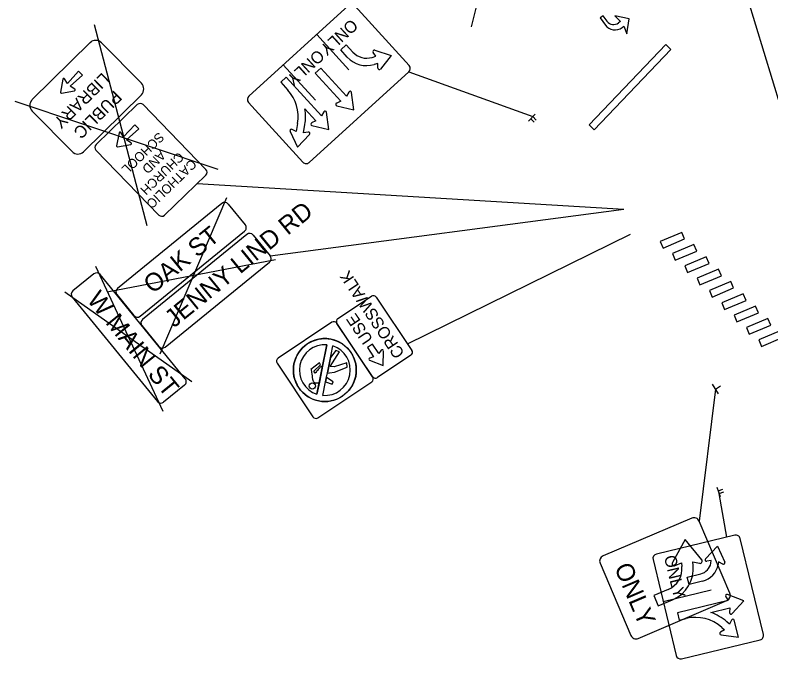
# Model space of a CAD drawing. Extents: x 1479394 to 1483660, y 379804 to 384342.
# Drawn here: x 1479394 to 1479604.6, y 379815.7 to 379995.2 of the extents above; entities that cross this region are included whole.
import ezdxf

# ---------------------------------------------------------------- set-up
doc = ezdxf.new("R2010")
doc.units = 0
for name, color, linetype in [('PM_P_Cells', 7, 'Continuous'), ('PM_P_Stop_Line', 7, 'Continuous'), ('RD_P_Text', 7, 'Continuous'), ('SC_Scratch15', 7, 'Continuous'), ('SC_Scratch3', 7, 'Continuous'), ('SH_Text', 7, 'Continuous')]:
    doc.layers.add(name, color=color, linetype=linetype)

msp = doc.modelspace()

# ---------------------------------------------------------------- linework, layer by layer
at = {"layer": 'PM_P_Cells'}
for p, q in [((1479557.84, 379995.03), (1479557.03, 379994.44)), ((1479557.03, 379994.44), (1479558.49, 379992.44)), ((1479558.94, 379993.53), (1479557.84, 379995.03)), ((1479565.07, 379994.18), (1479561.12, 379995.06)), ((1479561.12, 379995.06), (1479562.71, 379993.45)), ((1479564.44, 379989.95), (1479565.07, 379994.18)), ((1479562.71, 379993.45), (1479562.15, 379993.03)), ((1479563.12, 379991.76), (1479563.66, 379992.15)), ((1479563.66, 379992.15), (1479564.44, 379989.95)), ((1479564.44, 379989.95), (1479564.44, 379989.95))]:
    msp.add_line(p, q, dxfattribs=at)
for centre, radius, end in [((1479560.79, 379994.89), 2.3, 306.1769), ((1479561.14, 379994.38), 3.28, 307.0854)]:
    msp.add_arc(centre, radius, 216.1769, end, dxfattribs=at)
at = {"layer": 'PM_P_Stop_Line'}
msp.add_lwpolyline([(1479576.76, 379985.6), (1479575.34, 379987), (1479553.96, 379964.59), (1479555.4, 379963.2)], close=True, dxfattribs=at)
at = {"layer": 'RD_P_Text'}
for p, q in [((1479430.83, 379936.43), (1479416.15, 379992.52)), ((1479450.63, 379952.18), (1479394.05, 379971.11)), ((1479452.92, 379944.24), (1479434.33, 379900.66)), ((1479419.69, 379918.05), (1479466.63, 379927.1)), ((1479416.45, 379925.26), (1479435.18, 379884.77)), ((1479443.29, 379893.01), (1479407.91, 379917.97)), ((1479590.03, 379889.61), (1479588.31, 379892.31)), ((1479589.17, 379890.96), (1479590.52, 379891.82))]:
    msp.add_line(p, q, dxfattribs=at)
at = {"layer": 'SC_Scratch15'}
for p, q in [((1479578.23, 380065.44), (1479613.9, 379947.6)), ((1479487.06, 379979.98), (1479478.08, 379989.84)), ((1479484.77, 379985.51), (1479486.31, 379986.91)), ((1479486.59, 379983.51), (1479484.77, 379985.51)), ((1479486.31, 379986.91), (1479488.13, 379984.91)), ((1479494.25, 379985.44), (1479498.85, 379983.97)), ((1479493.49, 379983.43), (1479494.5, 379983.74)), ((1479494.5, 379983.74), (1479493.78, 379984.8)), ((1479498.85, 379983.97), (1479495.84, 379980.19)), ((1479477.74, 379971.5), (1479468.76, 379981.35)), ((1479495.11, 379981.74), (1479494.1, 379981.44)), ((1479495.09, 379980.46), (1479495.11, 379981.74)), ((1479479.22, 379980.46), (1479477.68, 379979.06)), ((1479477.68, 379979.06), (1479484.8, 379971.25)), ((1479486.34, 379972.65), (1479479.22, 379980.46)), ((1479503.73, 379979.39), (1479538.25, 379966.91)), ((1479469.59, 379977.88), (1479468.05, 379976.48)), ((1479479.37, 379967.15), (1479469.59, 379977.88)), ((1479468.05, 379976.48), (1479470.02, 379974.33)), ((1479486.99, 379973.77), (1479486.34, 379972.65)), ((1479488.42, 379968.82), (1479487.76, 379973.61)), ((1479484.8, 379971.25), (1479483.63, 379970.71)), ((1479474.79, 379969.08), (1479477.83, 379965.75)), ((1479480.02, 379968.26), (1479479.37, 379967.15)), ((1479483.71, 379969.92), (1479488.42, 379968.82)), ((1479481.45, 379963.32), (1479480.79, 379968.11)), ((1479537.03, 379965.63), (1479538.91, 379967.6)), ((1479537.69, 379966.32), (1479538.67, 379965.38)), ((1479537.97, 379966.61), (1479537.97, 379966.61)), ((1479537.97, 379966.61), (1479537.97, 379966.61)), ((1479538.25, 379966.91), (1479539.24, 379965.97)), ((1479472.74, 379965.03), (1479472.35, 379962.77)), ((1479474.41, 379962.42), (1479474.79, 379964.68)), ((1479477.83, 379965.75), (1479476.66, 379965.21)), ((1479476.74, 379964.42), (1479481.45, 379963.32)), ((1479470.64, 379962.81), (1479472.67, 379958.42)), ((1479472.35, 379962.77), (1479471.2, 379963.36)), ((1479475.68, 379962.59), (1479474.41, 379962.42)), ((1479472.67, 379958.42), (1479476.04, 379961.89)), ((1479503.38, 379903.52), (1479565.44, 379934.1)), ((1479478.13, 379889.51), (1479480.88, 379903.32)), ((1479493.65, 379903.47), (1479492.18, 379902.5)), ((1479481.78, 379897.22), (1479484.44, 379901.37)), ((1479481.78, 379897.22), (1479484.44, 379901.37)), ((1479483.39, 379901.73), (1479481.88, 379899.77)), ((1479483.39, 379901.73), (1479481.88, 379899.77)), ((1479484.44, 379901.37), (1479483.39, 379901.73)), ((1479484.44, 379901.37), (1479483.39, 379901.73)), ((1479492.18, 379902.5), (1479493.9, 379899.94)), ((1479496.06, 379901.78), (1479495.36, 379900.9)), ((1479496.58, 379897.5), (1479496.67, 379901.56)), ((1479481.88, 379899.77), (1479481.03, 379895.48)), ((1479492.8, 379898.97), (1479496.58, 379897.5)), ((1479493.9, 379899.93), (1479492.83, 379899.61)), ((1479493.9, 379899.94), (1479493.9, 379899.93)), ((1479494.69, 379900.33), (1479494.69, 379900.33)), ((1479478.83, 379898.25), (1479476.47, 379896.4)), ((1479478.83, 379898.25), (1479476.47, 379896.4)), ((1479477.23, 379895.97), (1479479.14, 379897.69)), ((1479477.23, 379895.97), (1479479.14, 379897.69)), ((1479478.8, 379892.91), (1479479.69, 379897.37)), ((1479479.14, 379897.69), (1479478.83, 379898.25)), ((1479479.14, 379897.69), (1479478.83, 379898.25)), ((1479482.93, 379897.13), (1479481.78, 379897.22)), ((1479482.93, 379897.13), (1479481.78, 379897.22)), ((1479486.45, 379898.22), (1479482.93, 379897.13)), ((1479486.45, 379898.22), (1479482.93, 379897.13)), ((1479482.99, 379895.68), (1479486.59, 379897.09)), ((1479482.99, 379895.68), (1479486.59, 379897.09)), ((1479486.59, 379897.09), (1479486.45, 379898.22)), ((1479486.59, 379897.09), (1479486.45, 379898.22)), ((1479476.47, 379896.4), (1479476.48, 379896.38)), ((1479476.47, 379896.4), (1479476.48, 379896.38)), ((1479477.62, 379895.35), (1479477.23, 379895.97)), ((1479477.62, 379895.35), (1479477.23, 379895.97)), ((1479481.03, 379895.48), (1479481.01, 379895.4)), ((1479481.01, 379895.4), (1479481.59, 379895.46)), ((1479481.01, 379895.4), (1479481.59, 379895.46)), ((1479481.59, 379895.46), (1479482.99, 379895.68)), ((1479481.59, 379895.46), (1479482.99, 379895.68)), ((1479478.77, 379892.76), (1479478.8, 379892.91)), ((1479480.53, 379892.98), (1479482.35, 379892.34)), ((1479480.53, 379892.98), (1479482.35, 379892.34)), ((1479480.76, 379894.13), (1479480.72, 379893.9)), ((1479482.61, 379893), (1479480.76, 379894.13)), ((1479482.61, 379893), (1479480.76, 379894.13)), ((1479482.35, 379892.34), (1479482.61, 379893)), ((1479482.35, 379892.34), (1479482.61, 379893)), ((1479589.17, 379890.96), (1479584.6, 379854.14)), ((1479590.51, 379860.91), (1479589.59, 379863.47)), ((1479589.91, 379862.57), (1479591.19, 379863.03)), ((1479590.05, 379862.19), (1479590.05, 379862.19)), ((1479590.05, 379862.19), (1479590.05, 379862.19)), ((1479590.19, 379861.8), (1479591.47, 379862.26)), ((1479592.33, 379849.65), (1479590.19, 379861.8)), ((1479580.69, 379848.97), (1479577.15, 379842.62)), ((1479585.33, 379843.37), (1479580.69, 379848.97)), ((1479586.35, 379843.64), (1479589.73, 379847.1)), ((1479589.73, 379847.1), (1479591.75, 379842.7)), ((1479577.93, 379841.73), (1479579.72, 379842.48)), ((1479579.72, 379842.48), (1479579.81, 379841.49)), ((1479582.92, 379841.78), (1479582.83, 379842.76)), ((1479582.83, 379842.76), (1479584.72, 379842.36)), ((1479587.98, 379843.11), (1479586.7, 379842.94)), ((1479587.86, 379842.43), (1479587.98, 379843.11)), ((1479590.03, 379842.75), (1479589.91, 379842.07)), ((1479591.18, 379842.16), (1479590.03, 379842.75)), ((1479581.3, 379838.52), (1479585.05, 379839.43)), ((1479581.79, 379836.5), (1479581.3, 379838.52)), ((1479585.54, 379837.4), (1479581.79, 379836.5)), ((1479575.97, 379835.07), (1479571.95, 379833.35)), ((1479587.97, 379834.88), (1479574.6, 379831.65)), ((1479597.04, 379831.93), (1479592.52, 379833.66)), ((1479571.95, 379833.35), (1479573.17, 379830.48)), ((1479573.17, 379830.48), (1479577.2, 379832.19)), ((1479592.68, 379831.95), (1479578.57, 379828.54)), ((1479592.02, 379833.05), (1479592.68, 379831.95)), ((1479593.81, 379828.33), (1479597.04, 379831.93)), ((1479587.88, 379828.65), (1479593.17, 379829.92)), ((1479593.17, 379829.92), (1479593.08, 379828.64)), ((1479578.57, 379828.54), (1479579.06, 379826.52)), ((1479579.06, 379826.52), (1479580.98, 379826.98)), ((1479593.06, 379825.37), (1479592.31, 379826.04)), ((1479593.59, 379826.55), (1479593.06, 379825.37)), ((1479595.53, 379821.78), (1479594.38, 379826.48)), ((1479591.67, 379823.82), (1479590.57, 379823.16)), ((1479590.92, 379824.49), (1479591.67, 379823.82)), ((1479590.73, 379822.39), (1479595.53, 379821.78))]:
    msp.add_line(p, q, dxfattribs=at)
for points in [[(1479486.89, 379997.87), (1479459.17, 379972.62)], [(1479503.81, 379981.16), (1479488.66, 379997.79)], [(1479476.01, 379954.14), (1479503.73, 379979.39)], [(1479459.09, 379970.85), (1479474.24, 379954.22)], [(1479483.97, 379910.59), (1479493.3, 379916.82)], [(1479494.67, 379916.55), (1479504.56, 379901.74)], [(1479482.26, 379909.57), (1479467.3, 379899.57)], [(1479493.65, 379894.33), (1479483.65, 379909.3)], [(1479493.6, 379894.41), (1479483.7, 379909.22)], [(1479480.87, 379903.32), (1479479.78, 379897.84), (1479479.78, 379897.84), (1479479.78, 379897.84), (1479478.8, 379892.91), (1479478.8, 379892.91)], [(1479480.72, 379893.9), (1479481.03, 379895.48), (1479482.05, 379900.63), (1479482.52, 379903)], [(1479495.36, 379900.91), (1479493.65, 379903.47)], [(1479504.29, 379900.37), (1479494.97, 379894.14)], [(1479467.02, 379898.18), (1479477.02, 379883.22)], [(1479478.8, 379892.91), (1479478.13, 379889.51)], [(1479478.41, 379882.94), (1479493.38, 379892.95)], [(1479478.8, 379892.91), (1479478.8, 379892.91)], [(1479479.78, 379889.18), (1479480.53, 379892.94), (1479480.71, 379893.9), (1479480.72, 379893.9)], [(1479480.72, 379893.9), (1479480.53, 379892.98), (1479480.53, 379892.98)], [(1479582.55, 379854.97), (1479557.83, 379844.43)], [(1479593.18, 379834.02), (1479584.6, 379854.14)], [(1479594.56, 379850.19), (1479572.69, 379844.91)], [(1479602.52, 379822.54), (1479596.06, 379849.27)], [(1479557, 379842.38), (1479565.58, 379822.26)], [(1479571.76, 379843.4), (1479578.22, 379816.67)], [(1479567.63, 379821.43), (1479592.35, 379831.97)], [(1479579.73, 379815.75), (1479601.6, 379821.03)]]:
    msp.add_lwpolyline(points, dxfattribs=at)
for centre, radius in [((1479480.33, 379896.25), 8.77), ((1479476.84, 379891.79), 0.864)]:
    msp.add_circle(centre, radius, dxfattribs=at)
for centre, radius, start, end in [((1479494.12, 379985.04), 0.417, 72.332, 214.2101), ((1479491.98, 379988.42), 7.29, 222.331, 286.8483), ((1479491.98, 379988.42), 5.21, 222.331, 286.8483), ((1479502.89, 379980.31), 1.25, 312.331, 42.331), ((1479495.51, 379980.45), 0.417, 179.4864, 321.3645), ((1479460.01, 379971.7), 1.25, 132.331, 222.331), ((1479461.85, 379966.89), 11.04, 350.3167, 42.331), ((1479487.35, 379973.56), 0.417, 7.8147, 149.6928), ((1479483.8, 379970.33), 0.417, 114.9691, 256.8472), ((1479461.85, 379966.89), 13.12, 350.3167, 9.6054), ((1479480.38, 379968.05), 0.417, 7.8147, 149.6928), ((1479476.84, 379964.83), 0.417, 114.9691, 256.8472), ((1479471.01, 379962.98), 0.417, 62.9548, 204.8329), ((1479475.74, 379962.18), 0.417, 315.8004, 97.6785), ((1479475.16, 379955.06), 1.25, 222.331, 312.331), ((1479493.84, 379916), 0.989, 33.7618, 123.7618), ((1479482.82, 379908.74), 1, 33.7618, 123.7618), ((1479484.52, 379909.77), 0.989, 123.7618, 213.7618), ((1479480.33, 379896.25), 8.77, 123.7618, 303.7618), ((1479480.33, 379896.25), 7.09, 85.5809, 251.9331), ((1479480.33, 379896.25), 7.09, 85.5809, 251.9331), ((1479480.33, 379896.25), 8.77, 303.7618, 123.7618), ((1479480.33, 379896.25), 7.09, 265.6097, 72.0097), ((1479480.33, 379896.25), 7.09, 265.6097, 72.0097), ((1479496.33, 379901.57), 0.342, 358.6825, 141.3996), ((1479503.74, 379901.19), 0.989, 303.7618, 33.7618), ((1479467.85, 379898.74), 1, 123.7618, 213.7618), ((1479492.92, 379899.29), 0.342, 106.124, 248.841), ((1479478.91, 379894.44), 1.54, 265.837, 265.8901), ((1479492.82, 379893.78), 1, 303.7618, 33.7618), ((1479494.42, 379894.96), 0.989, 213.7618, 303.7618), ((1479477.85, 379883.77), 1, 213.7618, 303.7618), ((1479583.16, 379853.53), 1.56, 23.083, 113.083), ((1479594.85, 379848.98), 1.25, 13.5814, 103.5814), ((1479558.44, 379842.99), 1.56, 113.083, 203.083), ((1479572.98, 379843.69), 1.25, 103.5814, 193.5814), ((1479577.69, 379842.31), 0.625, 150.8373, 292.6091), ((1479584.85, 379842.97), 0.625, 257.8766, 39.6484), ((1479584.17, 379843.07), 3.75, 283.5814, 350.1155), ((1479584.17, 379843.07), 5.83, 283.5814, 350.1155), ((1479586.65, 379843.35), 0.417, 135.5991, 277.4772), ((1479591.37, 379842.53), 0.417, 242.7536, 24.6317), ((1479573.48, 379840.91), 6.35, 293.083, 5.2217), ((1479573.48, 379840.91), 9.48, 293.083, 5.2256), ((1479592.37, 379833.27), 0.417, 69.0651, 210.9432), ((1479591.74, 379833.41), 1.56, 293.083, 23.083), ((1479583.57, 379816.25), 11.04, 48.2835, 103.5814), ((1479583.57, 379816.25), 13.13, 48.2835, 70.8559), ((1479593.5, 379828.61), 0.417, 176.2196, 318.0977), ((1479593.97, 379826.38), 0.417, 13.7672, 155.6453), ((1479590.78, 379822.8), 0.417, 120.9217, 262.7998), ((1479567.02, 379822.87), 1.56, 203.083, 293.083), ((1479601.31, 379822.25), 1.25, 283.5814, 13.5814), ((1479579.44, 379816.96), 1.25, 193.5814, 283.5814)]:
    msp.add_arc(centre, radius, start, end, dxfattribs=at)
for points in [[(1479479.69, 379897.37), (1479479.61, 379897.36), (1479479.41, 379897.3), (1479479.04, 379897.02), (1479478.75, 379896.72), (1479478.26, 379896.15), (1479477.92, 379895.74), (1479477.62, 379895.35)], [(1479479.69, 379897.37), (1479479.61, 379897.36), (1479479.41, 379897.3), (1479479.04, 379897.02), (1479478.75, 379896.72), (1479478.26, 379896.15), (1479477.92, 379895.74), (1479477.62, 379895.35)], [(1479476.48, 379896.38), (1479476.65, 379895.43), (1479476.89, 379893.93), (1479476.98, 379893.38), (1479477.05, 379893.22), (1479477.14, 379893.08), (1479477.36, 379892.74), (1479478.04, 379892.59), (1479478.49, 379892.7), (1479478.77, 379892.76)], [(1479476.48, 379896.38), (1479476.65, 379895.43), (1479476.89, 379893.93), (1479476.98, 379893.38), (1479477.05, 379893.22), (1479477.14, 379893.08), (1479477.36, 379892.74), (1479478.04, 379892.59), (1479478.49, 379892.7), (1479478.77, 379892.76)]]:
    msp.add_open_spline(points, degree=3, dxfattribs=at)
at = {"layer": 'SC_Scratch3'}
for p, q in [((1479579.77, 379934.64), (1479573.79, 379932.09)), ((1479580.55, 379932.8), (1479579.77, 379934.64)), ((1479574.57, 379930.25), (1479580.55, 379932.8)), ((1479573.79, 379932.09), (1479574.57, 379930.25)), ((1479583.15, 379931.26), (1479577.17, 379928.71)), ((1479583.94, 379929.42), (1479583.15, 379931.26)), ((1479577.17, 379928.71), (1479577.96, 379926.87)), ((1479577.96, 379926.87), (1479583.94, 379929.42)), ((1479586.58, 379927.83), (1479580.6, 379925.28)), ((1479587.36, 379925.99), (1479586.58, 379927.83)), ((1479580.6, 379925.28), (1479581.39, 379923.44)), ((1479581.39, 379923.44), (1479587.36, 379925.99)), ((1479590.01, 379924.4), (1479584.03, 379921.85)), ((1479590.79, 379922.56), (1479590.01, 379924.4)), ((1479584.81, 379920.01), (1479590.79, 379922.56)), ((1479584.03, 379921.85), (1479584.81, 379920.01)), ((1479593.44, 379920.97), (1479587.46, 379918.42)), ((1479594.22, 379919.13), (1479593.44, 379920.97)), ((1479587.46, 379918.42), (1479588.24, 379916.58)), ((1479588.24, 379916.58), (1479594.22, 379919.13)), ((1479596.9, 379917.51), (1479590.92, 379914.96)), ((1479591.7, 379913.12), (1479597.68, 379915.67)), ((1479597.68, 379915.67), (1479596.9, 379917.51)), ((1479590.92, 379914.96), (1479591.7, 379913.12)), ((1479600.33, 379914.08), (1479594.35, 379911.53)), ((1479601.11, 379912.24), (1479600.33, 379914.08)), ((1479594.35, 379911.53), (1479595.13, 379909.69)), ((1479595.13, 379909.69), (1479601.11, 379912.24)), ((1479603.76, 379910.65), (1479597.78, 379908.1)), ((1479604.54, 379908.81), (1479603.76, 379910.65)), ((1479597.78, 379908.1), (1479598.56, 379906.26)), ((1479598.56, 379906.26), (1479604.54, 379908.81)), ((1479607.19, 379907.22), (1479601.21, 379904.67)), ((1479601.99, 379902.83), (1479607.97, 379905.38)), ((1479601.21, 379904.67), (1479601.99, 379902.83))]:
    msp.add_line(p, q, dxfattribs=at)
at = {"layer": 'SH_Text'}
for p, q in [((1479547.02, 380097.79), (1479521.11, 379991.94)), ((1479411.75, 379979.56), (1479408.6, 379976.19)), ((1479411.75, 379979.56), (1479408.6, 379976.19)), ((1479412.84, 379978.46), (1479411.75, 379979.56)), ((1479412.84, 379978.46), (1479411.75, 379979.56)), ((1479407.36, 379977.37), (1479406.66, 379973.74)), ((1479407.36, 379977.37), (1479406.66, 379973.74)), ((1479408.6, 379976.19), (1479407.83, 379977.45)), ((1479408.6, 379976.19), (1479407.83, 379977.45)), ((1479409.42, 379975.36), (1479412.84, 379978.46)), ((1479409.42, 379975.36), (1479412.84, 379978.46)), ((1479409.78, 379976.63), (1479409.78, 379976.63)), ((1479410.67, 379974.56), (1479409.42, 379975.36)), ((1479410.67, 379974.56), (1479409.42, 379975.36)), ((1479406.95, 379973.45), (1479410.58, 379974.1)), ((1479406.95, 379973.45), (1479410.58, 379974.1)), ((1479427.41, 379964.62), (1479424.26, 379961.24)), ((1479427.41, 379964.62), (1479424.26, 379961.24)), ((1479428.5, 379963.51), (1479427.41, 379964.62)), ((1479428.5, 379963.51), (1479427.41, 379964.62)), ((1479423.02, 379962.42), (1479422.32, 379958.8)), ((1479423.02, 379962.42), (1479422.32, 379958.8)), ((1479424.26, 379961.24), (1479423.48, 379962.51)), ((1479424.26, 379961.24), (1479423.48, 379962.51)), ((1479425.08, 379960.41), (1479428.5, 379963.51)), ((1479425.08, 379960.41), (1479428.5, 379963.51)), ((1479426.33, 379959.62), (1479425.08, 379960.41)), ((1479426.33, 379959.62), (1479425.08, 379960.41)), ((1479422.61, 379958.51), (1479426.24, 379959.15)), ((1479422.61, 379958.51), (1479426.24, 379959.15)), ((1479444.79, 379948.27), (1479563.59, 379941.13)), ((1479465.09, 379928.09), (1479563.59, 379941.13))]:
    msp.add_line(p, q, dxfattribs=at)
for points in [[(1479398.8, 379971.64), (1479414.92, 379987.54)], [(1479418.12, 379987.51), (1479429.24, 379976.23)], [(1479429.22, 379973.03), (1479413.1, 379957.14)], [(1479409.9, 379957.16), (1479398.78, 379968.44)], [(1479416.59, 379959.14), (1479428.09, 379970.28)], [(1479429.7, 379970.25), (1479447.2, 379952.2)], [(1479434.07, 379939.47), (1479416.57, 379957.53)], [(1479447.18, 379950.58), (1479435.68, 379939.44)], [(1479451.65, 379942.72), (1479422.59, 379919.02)], [(1479453.41, 379942.54), (1479458.15, 379936.72)], [(1479428.9, 379911.27), (1479457.97, 379934.96)], [(1479458.59, 379934.08), (1479429.53, 379910.39)], [(1479460.35, 379933.9), (1479465.09, 379928.09)], [(1479435.84, 379902.64), (1479464.91, 379926.33)], [(1479415.98, 379923.05), (1479410.16, 379918.32)], [(1479441.43, 379893.81), (1479417.74, 379922.88)], [(1479409.98, 379916.56), (1479433.68, 379887.49)], [(1479422.41, 379917.27), (1479427.14, 379911.45)], [(1479429.35, 379908.63), (1479434.08, 379902.82)], [(1479441.25, 379892.05), (1479435.43, 379887.31)]]:
    msp.add_lwpolyline(points, dxfattribs=at)
for centre, radius, start, end in [((1479416.51, 379985.92), 2.26, 44.5972, 134.5972), ((1479407.61, 379977.32), 0.253, 31.621, 169.0943), ((1479407.61, 379977.32), 0.253, 31.621, 169.0943), ((1479410.54, 379974.35), 0.253, 280.1001, 57.5734), ((1479410.54, 379974.35), 0.253, 280.1001, 57.5734), ((1479427.63, 379974.64), 2.26, 314.5972, 44.5972), ((1479406.91, 379973.7), 0.253, 170.5036, 278.6908), ((1479406.91, 379973.7), 0.253, 170.5036, 278.6908), ((1479400.39, 379970.03), 2.26, 134.5972, 224.5972), ((1479428.88, 379969.46), 1.14, 44.1, 134.1), ((1479423.27, 379962.37), 0.253, 31.621, 169.0943), ((1479423.27, 379962.37), 0.253, 31.621, 169.0943), ((1479417.39, 379958.32), 1.14, 134.1, 224.1), ((1479422.57, 379958.76), 0.253, 170.5036, 278.6908), ((1479422.57, 379958.76), 0.253, 170.5036, 278.6908), ((1479426.2, 379959.4), 0.253, 280.1001, 57.5734), ((1479426.2, 379959.4), 0.253, 280.1001, 57.5734), ((1479411.51, 379958.75), 2.26, 224.5972, 314.5972), ((1479446.38, 379951.4), 1.14, 314.1, 44.1), ((1479452.44, 379941.75), 1.25, 39.179, 129.179), ((1479434.89, 379940.26), 1.14, 224.1, 314.1), ((1479457.18, 379935.93), 1.25, 309.179, 39.179), ((1479459.38, 379933.11), 1.25, 39.179, 129.179), ((1479464.12, 379927.3), 1.25, 309.179, 39.179), ((1479416.77, 379922.09), 1.25, 39.179, 129.179), ((1479410.95, 379917.35), 1.25, 129.179, 219.179), ((1479423.37, 379918.06), 1.25, 129.179, 219.179), ((1479428.11, 379912.24), 1.25, 219.179, 309.179), ((1479430.32, 379909.42), 1.25, 129.179, 219.179), ((1479435.05, 379903.61), 1.25, 219.179, 309.179), ((1479440.46, 379893.02), 1.25, 309.179, 39.179), ((1479434.64, 379888.28), 1.25, 219.179, 309.179)]:
    msp.add_arc(centre, radius, start, end, dxfattribs=at)

# ---------------------------------------------------------------- texts
at = {"layer": 'SC_Scratch15'}
for s, height, rotation, p in [('ONLY', 3.333, 222.331, (1479487.66, 379994.34)), ('ONLY', 3.333, 222.331, (1479478.34, 379985.85)), ('CROSSWALK', 3.296, 123.7618, (1479502.68, 379900.89)), ('USE', 3.296, 123.7618, (1479493.86, 379904.83)), ('ONLY', 3.333, 283.5814, (1479574.79, 379844.17)), ('ONLY', 5, 293.083, (1479560.89, 379841.22))]:
    msp.add_text(s, height=height, rotation=rotation, dxfattribs=at).set_placement(p)
at = {"layer": 'SH_Text'}
for s, height, rotation, p in [('LIBRARY', 3.395, 224.5972, (1479418.34, 379979.39)), ('PUBLIC', 3.395, 224.5972, (1479421.73, 379974.39)), ('SCHOOL', 2.6, 224.1, (1479434.04, 379962.74)), ('AND', 2.6, 224.1, (1479434.45, 379957.71)), ('CHURCH', 2.6, 224.1, (1479439.54, 379957.21)), ('CATHOLIC', 2.6, 224.1, (1479443.09, 379955.23)), ('      JENNY LIND RD', 5, 39.179, (1479429.65, 379900.81)), ('OAK ST', 5, 39.179, (1479432.39, 379917.34)), (' W MAIN ST', 5, 309.179, (1479412.7, 379917.18))]:
    msp.add_text(s, height=height, rotation=rotation, dxfattribs=at).set_placement(p)

doc.saveas('drawing.dxf')
